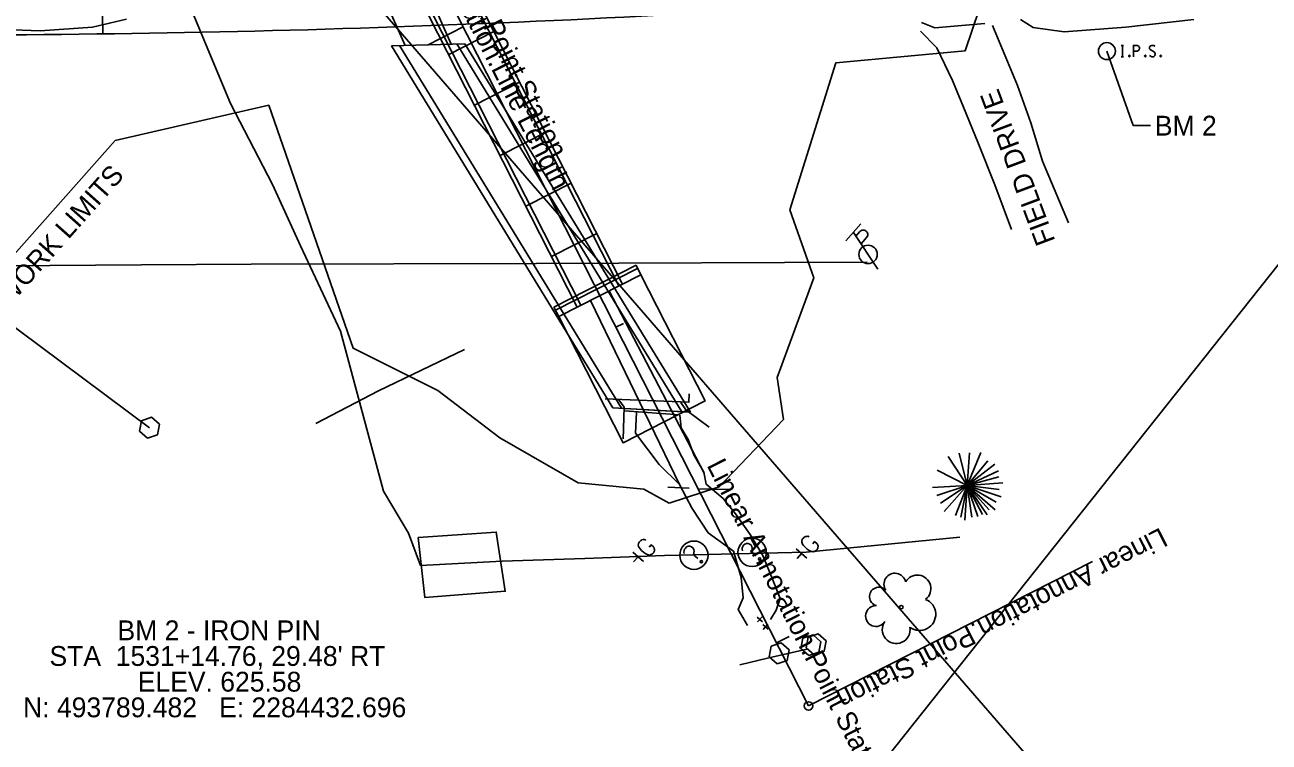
# Model space of a CAD drawing. Extents: x 0 to 1424, y 0 to 866.
# Drawn here: x 982.6 to 1158.3, y 543.7 to 645 of the extents above; entities that cross this region are included whole.
import ezdxf

# ---------------------------------------------------------------- set-up
doc = ezdxf.new("R2010")
doc.units = 0
for name, color, linetype in [('BR_X_SV_Deck_Top', 7, 'Continuous'), ('DR_P_Culvert', 7, 'Continuous'), ('DR_P_Drive_Pipe', 7, 'Continuous'), ('DR_P_Erosion_Control', 7, 'Continuous'), ('DT_P_Slope_Break_Line', 7, 'Continuous'), ('GE_P_Alignment_100_Bearings', 7, 'Continuous'), ('GE_P_Alignment_100_Cardinal_Points', 7, 'Continuous'), ('GE_P_Alignment_100_Distances', 7, 'Continuous'), ('GE_P_Alignment_100_Stations', 7, 'Continuous'), ('HY_P_Water_Edge', 7, 'Continuous'), ('MT_P_Cells', 7, 'Continuous'), ('MT_P_Channelizing_Line', 7, 'Continuous'), ('MT_P_Stop_Line', 7, 'Continuous'), ('MT_P_Temp_Road', 7, 'Continuous'), ('MT_P_Work_Area', 7, 'Continuous'), ('PF_P_Text', 7, 'Continuous'), ('PF_X_Ground_Line', 7, 'Continuous'), ('PV_P_Drive', 7, 'Continuous'), ('PV_P_Shoulder', 7, 'Continuous'), ('RD_P_GR_Lt', 7, 'Continuous'), ('SC_Scratch2', 7, 'Continuous'), ('TX_P_1', 7, 'Continuous'), ('TX_P_20', 7, 'Continuous'), ('TX_X_1', 7, 'Continuous'), ('XS_P_Finished_Grade', 7, 'Continuous')]:
    doc.layers.add(name, color=color, linetype=linetype)

msp = doc.modelspace()

# ---------------------------------------------------------------- linework, layer by layer
at = {"layer": 'BR_X_SV_Deck_Top'}
for points in [[(1109.08, 644.07), (1111.37, 641.71), (1113.59, 637.1), (1115.45, 632.56), (1117.26, 628.16), (1119.59, 622.37), (1121.93, 616.06)], [(1129.98, 617.03), (1126.32, 625.72), (1124.64, 631.12), (1122.78, 636.38), (1119.24, 644.85)]]:
    msp.add_lwpolyline(points, dxfattribs=at)
at = {"layer": 'DR_P_Culvert'}
for p, q in [((1008.65, 704.19), (1036.28, 642.05)), ((1015.14, 704.37), (1042.77, 642.24)), ((1044.47, 644.66), (1039.53, 642.15)), ((1034.34, 642), (1044.71, 642.29)), ((1034.34, 642), (1065.62, 590.91)), ((1035.49, 642.03), (1066.83, 590.84)), ((1043.56, 642.26), (1075.35, 590.34)), ((1044.71, 642.29), (1076.56, 590.27)), ((1076.56, 590.27), (1065.62, 590.91))]:
    msp.add_line(p, q, dxfattribs=at)
at = {"layer": 'DR_P_Drive_Pipe'}
for points in [[(1068.97, 590.26), (1068.8, 587.34), (1072.17, 582.88), (1075.01, 580.05), (1076.84, 576.66), (1079.1, 573.26), (1082.64, 570.65), (1083.74, 566.96), (1084.04, 564.08), (1083.33, 562.4), (1084.64, 560.15)], [(1075.08, 589.84), (1075.28, 588.05), (1076.24, 586.43), (1077.05, 584.27), (1078.48, 581.83), (1078.8, 580.11), (1081.2, 578.07), (1082.93, 575.93), (1085.03, 573.01), (1086.8, 570.04), (1088.24, 566.47), (1089.23, 563.97), (1088.7, 562.34), (1087.9, 561.01)]]:
    msp.add_lwpolyline(points, dxfattribs=at)
at = {"layer": 'DR_P_Erosion_Control'}
for points in [[(962.21, 618.42), (975.46, 606.45), (1000.17, 588.09)], [(1023.66, 588.69), (1032.49, 593.28), (1044.64, 599.12)]]:
    msp.add_lwpolyline(points, dxfattribs=at)
msp.add_lwpolyline([(1038.11, 572.6), (1049.14, 573.36), (1050.42, 565), (1039.06, 564.11)], close=True, dxfattribs=at)
at = {"layer": 'DT_P_Slope_Break_Line'}
msp.add_lwpolyline([(868.47, 609.78), (920.02, 610.51), (952.42, 610.79), (979.59, 610.93), (999.02, 611.08), (1014.52, 611.18), (1054.77, 611.28), (1101.52, 611.45)], dxfattribs=at)
at = {"layer": 'GE_P_Alignment_100_Bearings'}
for p, q in [((1362.43, 866.48), (920.11, 309.65)), ((874.07, 830.43), (1330.4, 303.64)), ((1135.39, 641.25), (1139.09, 630.73)), ((1139.09, 630.73), (1141.57, 630.73))]:
    msp.add_line(p, q, dxfattribs=at)
at = {"layer": 'GE_P_Alignment_100_Cardinal_Points'}
msp.add_line((1093.26, 548.81), (1133.36, 569.22), dxfattribs=at)
msp.add_circle((1093.26, 548.81), 0.6, dxfattribs=at)
at = {"layer": 'GE_P_Alignment_100_Stations'}
for p, q in [((1066.04, 602.28), (1067.11, 602.82)), ((1088.73, 557.72), (1090.51, 558.63))]:
    msp.add_line(p, q, dxfattribs=at)
at = {"layer": 'HY_P_Water_Edge'}
for p, q in [((1065.11, 607.42), (1078.51, 581.69)), ((1062.44, 606.05), (1075.01, 580.05))]:
    msp.add_line(p, q, dxfattribs=at)
for points in [[(999.87, 586.62), (1001.29, 587.1), (1001.59, 588.57), (1000.46, 589.56), (999.04, 589.08), (998.75, 587.61), (999.87, 586.62)], [(1094.04, 556.04), (1095.46, 556.52), (1095.75, 557.99), (1094.63, 558.98), (1093.21, 558.5), (1092.91, 557.03), (1094.04, 556.04)], [(1088.82, 554.77), (1090.24, 555.24), (1090.53, 556.71), (1089.41, 557.71), (1087.99, 557.23), (1087.69, 555.76), (1088.82, 554.77)], [(1093.3, 555.92), (1094.72, 556.4), (1095.01, 557.87), (1093.89, 558.86), (1092.47, 558.38), (1092.17, 556.91), (1093.3, 555.92)]]:
    msp.add_lwpolyline(points, dxfattribs=at)
at = {"layer": 'MT_P_Cells'}
for p, q in [((1069.93, 569.21), (1068.43, 570.53)), ((1069.18, 569.87), (1068.55, 569.15)), ((1093.03, 569.67), (1091.52, 570.99)), ((1092.28, 570.33), (1091.65, 569.61))]:
    msp.add_line(p, q, dxfattribs=at)
for points in [[(1070.25, 572.23), (1070.16, 572.28), (1070.05, 572.3), (1069.91, 572.29), (1069.73, 572.26), (1069.64, 572.21), (1069.57, 572.17), (1069.48, 572.09), (1069.32, 571.92), (1069.27, 571.83), (1069.25, 571.77), (1069.22, 571.69), (1069.21, 571.49), (1069.25, 571.32), (1069.32, 571.18), (1069.46, 571), (1069.67, 570.77), (1069.98, 570.49), (1070.25, 570.29), (1070.49, 570.18), (1070.75, 570.11), (1070.87, 570.13), (1071.01, 570.17), (1071.21, 570.28), (1071.35, 570.44), (1071.47, 570.63), (1071.49, 570.71), (1071.51, 570.8), (1071.5, 570.91), (1071.47, 571.05), (1071.39, 571.22), (1071.02, 571.55), (1070.74, 571.24)], [(1093.34, 572.69), (1093.26, 572.74), (1093.14, 572.76), (1093.01, 572.75), (1092.83, 572.72), (1092.73, 572.67), (1092.66, 572.63), (1092.57, 572.55), (1092.42, 572.38), (1092.37, 572.29), (1092.34, 572.23), (1092.32, 572.15), (1092.3, 571.95), (1092.34, 571.78), (1092.42, 571.64), (1092.56, 571.46), (1092.77, 571.23), (1093.08, 570.95), (1093.34, 570.75), (1093.59, 570.64), (1093.84, 570.57), (1093.97, 570.59), (1094.1, 570.63), (1094.31, 570.74), (1094.45, 570.9), (1094.56, 571.09), (1094.58, 571.17), (1094.61, 571.26), (1094.6, 571.37), (1094.56, 571.51), (1094.48, 571.68), (1094.11, 572.01), (1093.84, 571.7)]]:
    msp.add_lwpolyline(points, dxfattribs=at)
at = {"layer": 'MT_P_Channelizing_Line'}
for p, q in [((1076.35, 590.28), (1067.24, 590.81)), ((1067.45, 590.86), (1067.45, 590.86))]:
    msp.add_line(p, q, dxfattribs=at)
for points in [[(1067.24, 590.46), (1075.02, 589.92)], [(1093, 556.82), (1087.45, 555.54), (1083.55, 554.62)]]:
    msp.add_lwpolyline(points, dxfattribs=at)
at = {"layer": 'MT_P_Stop_Line'}
for p, q in [((1100.65, 616.85), (1098.54, 614.45)), ((1099.59, 615.65), (1103.03, 610.48)), ((1099.94, 615.13), (1100.5, 615.77)), ((1100.67, 614.03), (1101.46, 614.93))]:
    msp.add_line(p, q, dxfattribs=at)
msp.add_circle((1101.66, 612.55), 1.3, dxfattribs=at)
msp.add_arc((1100.99, 615.36), 0.638, 317.516, 139.7626, dxfattribs=at)
at = {"layer": 'MT_P_Temp_Road'}
for points in [[(1137.41, 642.05), (1137.76, 642.05)], [(1137.59, 640.45), (1137.59, 642.05)], [(1139.15, 640.45), (1139.15, 642.05), (1139.68, 642.05), (1139.74, 642.04), (1139.81, 642.02), (1139.85, 641.99), (1139.88, 641.96), (1139.92, 641.9), (1139.96, 641.84), (1139.98, 641.74), (1139.98, 641.59), (1139.97, 641.54), (1139.94, 641.46), (1139.9, 641.37), (1139.86, 641.34), (1139.82, 641.31), (1139.77, 641.28), (1139.68, 641.27), (1139.15, 641.27)], [(1142.16, 641.94), (1142.14, 641.96), (1142.11, 641.99), (1142.01, 642.03), (1141.88, 642.05), (1141.8, 642.05), (1141.76, 642.05), (1141.62, 642.02), (1141.5, 641.94), (1141.42, 641.84), (1141.4, 641.74), (1141.4, 641.66), (1141.42, 641.56), (1141.51, 641.47), (1142.12, 641.1), (1142.17, 641.05), (1142.19, 640.99), (1142.22, 640.92), (1142.22, 640.84), (1142.2, 640.77), (1142.19, 640.72), (1142.17, 640.65), (1142.15, 640.6), (1142.13, 640.57), (1142.09, 640.53), (1142.06, 640.5), (1142.02, 640.48), (1141.98, 640.47), (1141.88, 640.45), (1141.73, 640.45), (1141.63, 640.48), (1141.49, 640.57), (1141.4, 640.64)], [(1137.41, 640.45), (1137.76, 640.45)], [(1138.55, 640.67), (1138.6, 640.67), (1138.63, 640.64), (1138.67, 640.59), (1138.67, 640.53), (1138.63, 640.48), (1138.6, 640.45), (1138.55, 640.45), (1138.51, 640.48), (1138.48, 640.53), (1138.48, 640.59), (1138.51, 640.64), (1138.55, 640.67)], [(1140.79, 640.67), (1140.85, 640.67), (1140.88, 640.64), (1140.91, 640.59), (1140.91, 640.53), (1140.88, 640.48), (1140.85, 640.45), (1140.79, 640.45), (1140.76, 640.48), (1140.73, 640.53), (1140.73, 640.59), (1140.76, 640.64), (1140.79, 640.67)], [(1142.98, 640.67), (1143.03, 640.67), (1143.06, 640.64), (1143.1, 640.59), (1143.1, 640.53), (1143.06, 640.48), (1143.03, 640.45), (1142.98, 640.45), (1142.94, 640.48), (1142.91, 640.53), (1142.91, 640.59), (1142.94, 640.64), (1142.98, 640.67)]]:
    msp.add_lwpolyline(points, dxfattribs=at)
msp.add_circle((1135.39, 641.25), 1.2, dxfattribs=at)
at = {"layer": 'MT_P_Work_Area'}
for p, q in [((1015.63, 707.91), (1066.45, 608.1)), ((1066.97, 608.36), (1016.15, 708.17)), ((1009.77, 704.92), (1060.58, 605.11)), ((1010.29, 705.18), (1061.1, 605.37)), ((1042.43, 640.76), (1048.82, 644.01)), ((1046.06, 633.63), (1052.45, 636.88)), ((1049.69, 626.5), (1056.08, 629.75)), ((1053.32, 619.37), (1059.71, 622.62)), ((1056.95, 612.24), (1063.34, 615.49)), ((1057.3, 605.12), (1068.89, 611.02)), ((1057.53, 604.68), (1069.11, 610.58)), ((1069.57, 609.68), (1068.89, 611.02)), ((1057.98, 603.79), (1069.57, 609.68)), ((1057.3, 605.12), (1057.98, 603.79))]:
    msp.add_line(p, q, dxfattribs=at)
at = {"layer": 'PF_P_Text'}
for points in [[(1064.55, 592.16), (1076.36, 591.69), (1076.4, 592.89)], [(1067.07, 586.54), (1067.23, 591.01), (1066.44, 592)], [(1079.22, 588.18), (1075.93, 590.6), (1075.21, 591.65)]]:
    msp.add_lwpolyline(points, dxfattribs=at)
at = {"layer": 'PF_X_Ground_Line'}
for p, q in [((1069.57, 609.68), (1078.64, 591.86)), ((1057.98, 603.79), (1067.05, 585.96)), ((1067.05, 585.96), (1078.64, 591.86))]:
    msp.add_line(p, q, dxfattribs=at)
msp.add_lwpolyline([(1057.98, 603.79), (1067.05, 585.96), (1078.64, 591.86), (1069.57, 609.68), (1057.98, 603.79)], close=True, dxfattribs=at)
at = {"layer": 'PV_P_Drive'}
for points in [[(943.54, 731.24), (956.01, 731.4), (967.27, 731.12), (972.12, 730.53), (979.8, 726.97), (983.81, 719.8), (987.99, 710.05), (990.77, 698.45), (992.8, 689.85), (995.65, 680.91), (1004.63, 650.62), (1011.63, 633.87), (1017.52, 622.44), (1021.49, 613.78), (1027.14, 601.74), (1033.23, 579.15), (1036.77, 573.22), (1038.45, 568.65), (1049.99, 569.23), (1061.67, 569.6), (1072.89, 570.06), (1092.92, 570.52), (1114.64, 572.62)], [(1073.37, 579.7), (1076.41, 579.56)], [(1077.87, 579.47), (1082.08, 579.35)]]:
    msp.add_lwpolyline(points, dxfattribs=at)
at = {"layer": 'PV_P_Shoulder'}
msp.add_line((993.56, 643.69), (993.45, 651.68), dxfattribs=at)
msp.add_arc((968.3, 2573.38), 1929.86, 269.25, 273.96964, dxfattribs=at)
at = {"layer": 'RD_P_GR_Lt'}
for p, q in [((1115.68, 579.95), (1112.98, 584)), ((1115.68, 579.95), (1114.51, 584.51)), ((1115.68, 579.95), (1117.6, 584.57)), ((1115.68, 579.95), (1115.99, 584.55)), ((1115.68, 579.95), (1111.4, 582.07)), ((1115.68, 579.95), (1118.59, 583.4)), ((1115.68, 579.95), (1119.59, 582.94)), ((1115.68, 579.95), (1120.08, 582.02)), ((1115.68, 579.95), (1120.12, 581.13)), ((1115.68, 579.95), (1120.69, 580.32)), ((1115.68, 579.95), (1110.75, 579.63)), ((1115.68, 579.95), (1111.37, 578.54)), ((1115.68, 579.95), (1111.87, 577.42)), ((1112.42, 576.25), (1115.68, 579.95)), ((1115.68, 579.95), (1114.01, 575.7)), ((1115.68, 579.95), (1114.76, 575.45)), ((1115.68, 579.95), (1115.34, 575.04)), ((1115.68, 579.95), (1116.33, 575.45)), ((1115.68, 579.95), (1117.16, 575.56)), ((1115.68, 579.95), (1117.83, 575.83)), ((1115.68, 579.95), (1118.49, 575.79)), ((1115.68, 579.95), (1118.76, 576.51)), ((1119.61, 576.49), (1115.68, 579.95)), ((1115.68, 579.95), (1119.77, 577.58)), ((1115.68, 579.95), (1120.46, 578.32)), ((1115.68, 579.95), (1120.2, 579.35))]:
    msp.add_line(p, q, dxfattribs=at)
msp.add_circle((1106.36, 562.75), 0.24, dxfattribs=at)
for centre, radius, start, end in [((1105.45, 565.99), 1.55, 12.4693, 213.6769), ((1108.62, 565.37), 1.91, 307.7847, 150.099), ((1103.18, 564.24), 1.32, 42.644, 254.6135), ((1102.78, 561.5), 1.47, 87.7019, 328.1806), ((1108.94, 561.74), 2.28, 233.5869, 68.0965), ((1105.64, 559.59), 1.97, 144.8115, 9.2131)]:
    msp.add_arc(centre, radius, start, end, dxfattribs=at)
at = {"layer": 'SC_Scratch2'}
msp.add_line((997.99, 735.95), (1093.26, 548.81), dxfattribs=at)
at = {"layer": 'TX_P_1'}
for points in [[(996.9, 645.75), (992.13, 644.64), (984.72, 644.14), (972.01, 644.6)], [(1118.16, 645.16), (1111.07, 644.56), (1109.23, 645.29)], [(1147.66, 645.73), (1138.07, 644.63), (1129.35, 643.96), (1124.98, 644.61), (1123.18, 645.71)]]:
    msp.add_lwpolyline(points, dxfattribs=at)
at = {"layer": 'TX_P_20'}
for p, q in [((1077.62, 569.6), (1077.27, 569.91)), ((1085.86, 569.99), (1085.5, 570.31))]:
    msp.add_line(p, q, dxfattribs=at)
for centre, radius in [((1077.06, 570.09), 2), ((1085.29, 570.49), 2), ((1086.35, 569.56), 0.17), ((1078.12, 569.16), 0.17)]:
    msp.add_circle(centre, radius, dxfattribs=at)
for centre, radius, start, end in [((1076.39, 570.67), 0.688, 340.5723, 141.0977), ((1084.64, 570.98), 0.754, 136.9633, 201.1779), ((1084.62, 571.06), 0.688, 340.5723, 141.0977), ((1076.41, 570.58), 0.754, 136.9633, 201.1779), ((1077.62, 570.38), 0.587, 174.1011, 232.7223), ((1085.86, 570.77), 0.587, 174.1011, 232.7223)]:
    msp.add_arc(centre, radius, start, end, dxfattribs=at)
at = {"layer": 'TX_X_1'}
for p, q in [((1089.74, 589.27), (1088.83, 595.17)), ((1080.65, 579.76), (1089.74, 589.27)), ((1070.01, 579.39), (1073.56, 577.42)), ((1073.56, 577.42), (1080.65, 579.76))]:
    msp.add_line(p, q, dxfattribs=at)
for points in [[(1076.23, 709.64), (1096.66, 685.48), (1116.93, 684.78), (1119.41, 653.31), (1115.36, 641.29)], [(1115.36, 641.29), (1097.12, 639.62), (1090.6, 618.84)], [(968.88, 598.84), (995.33, 628.65), (1017.04, 633.64)], [(1017.04, 633.64), (1028.92, 599.31), (1040.9, 593.34)], [(1088.83, 595.17), (1094.01, 609.27), (1090.6, 618.84)], [(1040.9, 593.34), (1049.66, 586.67), (1060.73, 580.29), (1070.01, 579.39)]]:
    msp.add_lwpolyline(points, dxfattribs=at)
at = {"layer": 'XS_P_Finished_Grade'}
for p, q in [((1086.01, 561.36), (1086.76, 560.7)), ((1086.06, 560.66), (1086.72, 561.41)), ((1086.39, 561.03), (1086.39, 561.03)), ((1086.79, 560.31), (1087.54, 559.65)), ((1086.83, 559.61), (1087.49, 560.36)), ((1087.16, 559.98), (1087.16, 559.98))]:
    msp.add_line(p, q, dxfattribs=at)

# ---------------------------------------------------------------- texts
at = {"layer": 'GE_P_Alignment_100_Bearings'}
for s, rotation, p in [('FIELD DRIVE', 110.5441, (1128.14, 614.47)), ('WORK LIMITS', 48.4222, (980.29, 605.1))]:
    msp.add_text(s, height=2.8, rotation=rotation, dxfattribs=at).set_placement(p)
for s, p in [('BM 2', (1142.17, 629.33)), ('BM 2 - IRON PIN', (995.65, 558.08)), ("STA  1531+14.76, 29.48' RT", (986.04, 554.46)), ('ELEV. 625.58', (998.51, 550.83)), ('N: 493789.482   E: 2284432.696', (982.31, 547.21))]:
    msp.add_text(s, height=2.8, dxfattribs=at).set_placement(p)
at = {"layer": 'GE_P_Alignment_100_Cardinal_Points'}
msp.add_text('Linear Annotation.Point Station', height=2.8, rotation=206.98, dxfattribs=at).set_placement((1142.97, 574.06))
at = {"layer": 'GE_P_Alignment_100_Distances'}
msp.add_text('Linear Annotation.Line Length', height=2.8, rotation=296.98, dxfattribs=at).set_placement((1034.57, 665.88))
at = {"layer": 'GE_P_Alignment_100_Stations'}
for p in [(1033.45, 671.91), (1078.82, 582.79)]:
    msp.add_text('Linear Annotation.Point Station', height=2.8, rotation=296.98, dxfattribs=at).set_placement(p)

doc.saveas('drawing.dxf')
